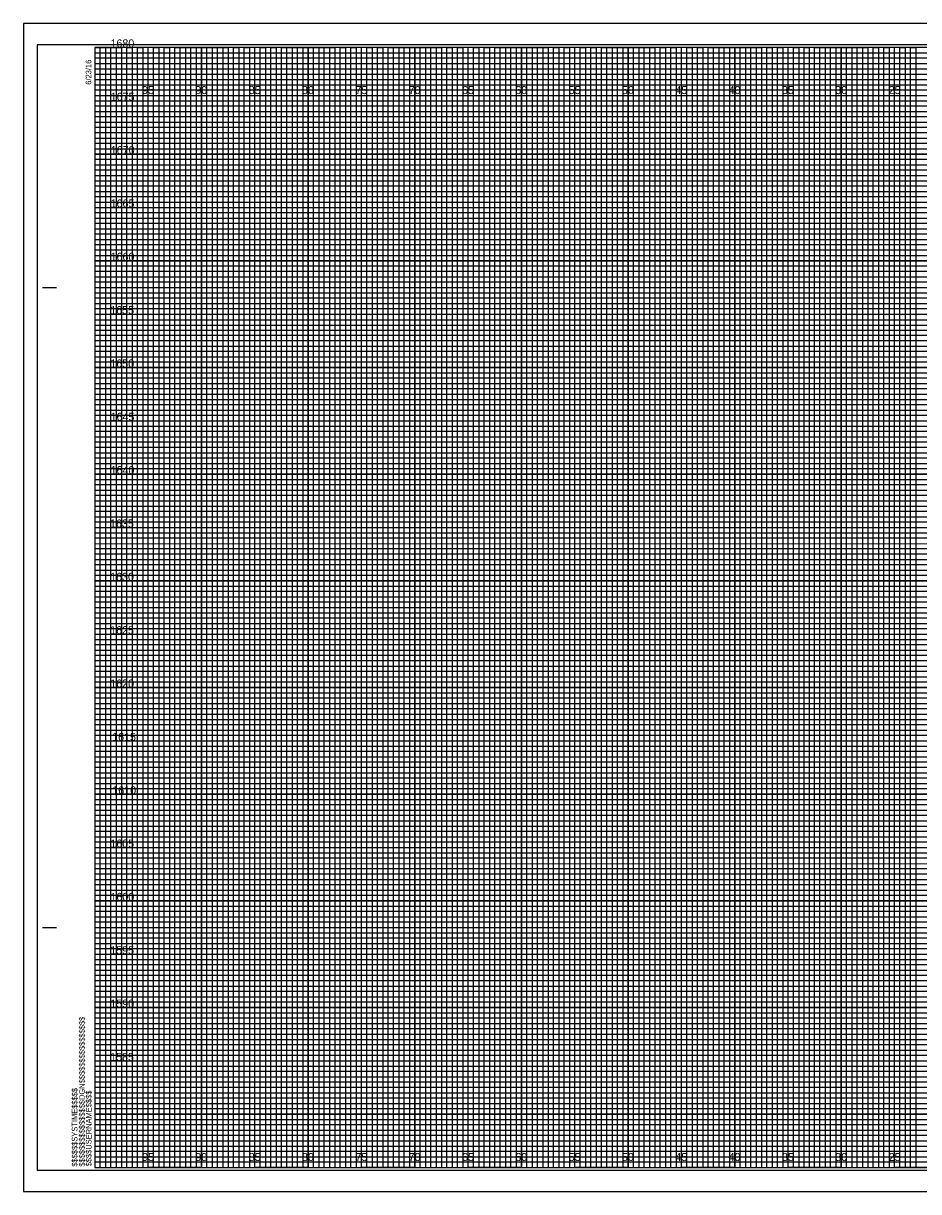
# Model space of a CAD drawing. Extents: x -8289 to 162, y -2 to 23207.
# Drawn here: x -6.7 to 77.2, y 547.8 to 657.2 of the extents above; entities that cross this region are included whole.
import ezdxf

# ---------------------------------------------------------------- set-up
doc = ezdxf.new("R2010")
doc.units = 0
for name, color, linetype in [('Prop XS Elevation Labels', 7, 'Continuous'), ('Prop XS Offset Labels', 7, 'Continuous'), ('Sheet Cross Section CELL', 7, 'Continuous'), ('Sheet Cross Section Grid Major CELL', 7, 'Continuous'), ('Sheet Cross Section Grid Middle CELL', 7, 'Continuous'), ('Sheet Cross Section Grid Minor 1 CELL', 7, 'Continuous'), ('Sheet Cross Section Grid Minor 2 CELL', 7, 'Continuous'), ('Sheet Cutting Line CELL', 7, 'Continuous'), ('Sheet DOT Grid CELL', 7, 'Continuous'), ('Sheet Plot Border Inside CELL', 7, 'Continuous'), ('Sheet Plot Border Outside CELL', 7, 'Continuous')]:
    doc.layers.add(name, color=color, linetype=linetype)

msp = doc.modelspace()

# ---------------------------------------------------------------- linework, layer by layer
at = {"layer": 'Sheet Cross Section CELL'}
for p, q in [((-4.9, 632.5), (-3.65, 632.5)), ((-4.85, 632.5), (-3.6, 632.5)), ((-4.9, 572.5), (-3.65, 572.5)), ((-4.85, 572.5), (-3.6, 572.5)), ((0, 550), (0, 550)), ((0, 550), (0, 550)), ((0, 550), (0, 550)), ((0, 550), (0, 550)), ((0, 550), (0, 550)), ((0, 550), (0, 550)), ((0, 550), (0, 550))]:
    msp.add_line(p, q, dxfattribs=at)
msp.add_lwpolyline([(160, 655), (0, 655), (0, 550), (160, 550)], close=True, dxfattribs=at)
at = {"layer": 'Sheet Cross Section Grid Major CELL'}
for p, q in [((5, 655), (0, 655)), ((5, 550), (5, 655)), ((15, 655), (10, 655)), ((10, 655), (10, 550)), ((15, 550), (15, 655)), ((25, 655), (20, 655)), ((20, 655), (20, 550)), ((25, 550), (25, 655)), ((35, 655), (30, 655)), ((30, 655), (30, 550)), ((35, 550), (35, 655)), ((45, 655), (40, 655)), ((40, 655), (40, 550)), ((45, 550), (45, 655)), ((55, 655), (50, 655)), ((50, 655), (50, 550)), ((55, 550), (55, 655)), ((65, 655), (60, 655)), ((60, 655), (60, 550)), ((65, 550), (65, 655)), ((75, 655), (70, 655)), ((70, 655), (70, 550)), ((75, 550), (75, 655)), ((10, 550), (5, 550)), ((20, 550), (15, 550)), ((30, 550), (25, 550)), ((40, 550), (35, 550)), ((50, 550), (45, 550)), ((60, 550), (55, 550)), ((70, 550), (65, 550)), ((80, 550), (75, 550))]:
    msp.add_line(p, q, dxfattribs=at)
for points in [[(0, 650), (160, 650), (160, 645), (0, 645)], [(0, 640), (160, 640), (160, 635), (0, 635)], [(0, 630), (160, 630), (160, 625), (0, 625)], [(0, 620), (160, 620), (160, 615), (0, 615)], [(0, 610), (160, 610), (160, 605), (0, 605)], [(0, 600), (160, 600), (160, 595), (0, 595)], [(0, 590), (160, 590), (160, 585), (0, 585)], [(0, 580), (160, 580), (160, 575), (0, 575)], [(0, 570), (160, 570), (160, 565), (0, 565)], [(0, 560), (160, 560), (160, 555), (0, 555)]]:
    msp.add_lwpolyline(points, dxfattribs=at)
at = {"layer": 'Sheet Cross Section Grid Middle CELL'}
for points in [[(0, 655), (2.5, 655), (2.5, 550), (7.5, 550), (7.5, 655), (12.5, 655), (12.5, 550), (17.5, 550), (17.5, 655), (22.5, 655), (22.5, 550), (27.5, 550), (27.5, 655), (32.5, 655), (32.5, 550), (37.5, 550), (37.5, 655), (42.5, 655), (42.5, 550), (47.5, 550), (47.5, 655), (52.5, 655), (52.5, 550), (57.5, 550), (57.5, 655), (62.5, 655), (62.5, 550), (67.5, 550), (67.5, 655), (72.5, 655), (72.5, 550), (77.5, 550)], [(0, 652.5), (137.5, 652.5)], [(0, 642.5), (160, 642.5), (160, 647.5), (0, 647.5)], [(0, 632.5), (160, 632.5), (160, 637.5), (0, 637.5)], [(0, 622.5), (160, 622.5), (160, 627.5), (0, 627.5)], [(0, 612.5), (160, 612.5), (160, 617.5), (0, 617.5)], [(0, 602.5), (160, 602.5), (160, 607.5), (0, 607.5)], [(0, 592.5), (160, 592.5), (160, 597.5), (0, 597.5)], [(0, 582.5), (160, 582.5), (160, 587.5), (0, 587.5)], [(0, 572.5), (160, 572.5), (160, 577.5), (0, 577.5)], [(0, 562.5), (160, 562.5), (160, 567.5), (0, 567.5)], [(0, 552.5), (160, 552.5), (160, 557.5), (0, 557.5)]]:
    msp.add_lwpolyline(points, dxfattribs=at)
at = {"layer": 'Sheet Cross Section Grid Minor 1 CELL'}
for p, q in [((0, 654.5), (130, 654.5)), ((130, 653.99), (0, 653.99)), ((0, 653.99), (0, 653.5)), ((0, 653.5), (130, 653.5)), ((130, 652.95), (0, 652.95)), ((0, 652.95), (0, 652)), ((0, 652), (160, 652))]:
    msp.add_line(p, q, dxfattribs=at)
for points in [[(0, 651.5), (135, 651.5), (160, 651.5), (160, 651), (0, 651)], [(0, 650.5), (160, 650.5), (160, 649.5), (0, 649.5)], [(0, 649), (160, 649), (160, 648.5), (0, 648.49)], [(0, 648), (160, 648), (160, 647), (0, 647)], [(0, 646.5), (160, 646.5), (160, 646), (0, 646)], [(0, 645.5), (160, 645.5), (160, 644.5), (0, 644.5)], [(0, 644), (160, 644), (160, 643.5), (0, 643.5)], [(0, 643), (160, 643), (160, 642), (0, 642)], [(0, 641.5), (160, 641.5), (160, 641), (0, 641)], [(0, 640.5), (160, 640.5), (160, 639.5), (0, 639.5)], [(0, 639), (160, 639), (160, 638.5), (0, 638.5)], [(0, 638), (160, 638), (160, 636.98), (160, 636.5), (160, 636), (0, 636)], [(0, 637), (160, 637), (160, 636.5), (0, 636.5)], [(0, 635.5), (160, 635.5), (160, 634.5), (0, 634.51)], [(0, 634.51), (160, 634.5), (160, 634), (0, 634)], [(0, 633.5), (160, 633.5), (160, 633), (0, 633)], [(0, 632), (160, 632), (160, 631.5), (0, 631.5)], [(0, 631), (160, 631), (160, 630.5), (0, 630.5)], [(-0.04, 629.45), (160, 629.45), (160, 628.94), (-0.04, 628.94)], [(0, 628.5), (160, 628.5), (160, 628), (0, 628)], [(0, 627), (160, 627), (160, 626.5), (0, 626.5)], [(0, 626), (160, 626), (160, 625.5), (0, 625.5)], [(0, 624.5), (160, 624.5), (160, 624), (0, 624)], [(0, 623.5), (160, 623.5), (160, 623), (0, 623)], [(0, 622), (160, 622), (160, 621.5), (0, 621.5)], [(0, 621), (160, 621), (160, 620.5), (0, 620.5)], [(0, 619.5), (160, 619.5), (160, 618.99), (0, 619)], [(0, 618.5), (160, 618.5), (160, 618), (0, 618)], [(0, 617), (160, 617), (160, 616.5), (0, 616.5)], [(0, 616), (160, 616), (160, 615.5), (0, 615.5)], [(0, 614.5), (160, 614.5), (160, 614), (0, 614)], [(0, 613.5), (160, 613.5), (160, 613), (0, 613)], [(0, 612), (160, 612), (160, 611.5), (0, 611.5)], [(0, 611), (160, 611), (160, 610.5), (0, 610.5)], [(0, 609.5), (160, 609.5), (160, 609), (0, 609)], [(0, 608.5), (160.03, 608.46), (160, 608), (0, 608)], [(0, 607), (160, 607), (160, 606.5), (0, 606.5)], [(0, 606), (160, 606), (160, 605.5), (0, 605.5)], [(0, 604.5), (160, 604.5), (160, 604), (0, 604)], [(0, 603.5), (160, 603.5), (160, 603), (0, 603)], [(0, 602), (160, 602), (160, 601.5), (0, 601.5)], [(0, 601), (160, 601), (160, 600.5), (0, 600.5)], [(0, 599.5), (160, 599.5), (160, 599), (0, 599)], [(0, 598.5), (160, 598.5), (160, 598), (0, 598)], [(0, 597), (160, 597), (160, 596.5), (0, 596.5)], [(0, 596), (160, 596), (160, 595.5), (0, 595.5)], [(0, 594.5), (160, 594.5), (160, 594), (0, 594)], [(0, 593.5), (160, 593.5), (160, 593), (0, 593)], [(0, 592), (160, 592), (160, 591.5), (0, 591.5)], [(0, 591), (160, 591), (160, 590.5), (0, 590.5)], [(0, 589.5), (160, 589.5), (160, 588.99), (0, 589)], [(0, 588.5), (160, 588.5), (160, 588), (0, 588)], [(0, 587), (160, 587), (160, 586.5), (0, 586.5)], [(0, 586), (160, 586), (160, 585.5), (0, 585.5)], [(0, 584.5), (160, 584.5), (160, 584), (0, 584)], [(0, 583.5), (160, 583.5), (160, 583), (0, 583)], [(0, 582), (160, 582), (160, 581.5), (0, 581.5)], [(0, 581), (160, 581), (160, 580.5), (0, 580.5)], [(0, 579.5), (160, 579.5), (160, 579), (0, 579)], [(0, 578.5), (160.03, 578.46), (160, 578), (0, 578)], [(0, 577), (160, 577), (160, 576.5), (0, 576.5)], [(0, 576), (160, 576), (160, 575.5), (0, 575.5)], [(0, 574.5), (160, 574.5), (160, 574), (0, 574)], [(0, 573.5), (160, 573.5), (160, 573), (0, 573)], [(0, 572), (160, 572), (160, 571.5), (0, 571.5)], [(0, 571), (160, 571), (160, 570.5), (0, 570.5)], [(0, 569.5), (160, 569.5), (160, 569), (0, 569)], [(0, 568.5), (160, 568.5), (160, 568), (0, 568)], [(0, 567), (160, 567), (160, 566.5), (0, 566.5)], [(0, 566), (160, 566), (160, 565.5), (0, 565.5)], [(0, 564.5), (160, 564.5), (160, 564), (0, 564)], [(0, 563.5), (160, 563.5), (160, 563), (0, 563)], [(0, 562), (160, 562), (160, 561.5), (0, 561.5)], [(0, 561), (160, 561), (160, 560.5), (0, 560.5)], [(0, 559.5), (160, 559.5), (160, 559), (0, 559)], [(0, 558.5), (160, 558.5), (160, 558), (0, 558)], [(0, 557), (160, 557), (160, 556.5), (0, 556.5)], [(0, 556), (160, 556), (160, 555.5), (0, 555.5)], [(0, 554.5), (160, 554.5), (160, 554), (0, 554)], [(0, 553.5), (160, 553.5), (160, 553), (0, 553)], [(0, 552), (160, 552), (160, 551.5), (0, 551.5)], [(0, 551), (160, 551), (160, 550.5), (0, 550.5)]]:
    msp.add_lwpolyline(points, dxfattribs=at)
at = {"layer": 'Sheet Cross Section Grid Minor 2 CELL'}
for points in [[(0, 550), (0.5, 550), (0.5, 655), (1, 655), (1, 550)], [(1, 550), (1.5, 550), (1.5, 655), (2, 655), (2, 550)], [(2.5, 550), (3, 550), (3, 655), (3.5, 655), (3.5, 550)], [(3.5, 550), (4, 550), (4, 655), (4.5, 655), (4.5, 550)], [(5, 550), (5.5, 550), (5.5, 655), (6, 655), (6, 550)], [(6, 550), (6.5, 550), (6.5, 655), (7, 655), (7, 550)], [(7.5, 550), (8, 550), (8, 655), (8.5, 655), (8.5, 550)], [(8.5, 550), (9, 550), (9, 655), (9.5, 655), (9.5, 550)], [(10, 550), (10.5, 550), (10.5, 655), (11, 655), (11, 550)], [(11, 550), (11.5, 550), (11.5, 655), (12, 655), (12, 550)], [(12.5, 550), (13, 550), (13, 655), (13.5, 655), (13.5, 550)], [(13.5, 550), (14, 550), (14, 655), (14.5, 655), (14.5, 550)], [(15, 550), (15.5, 550), (15.5, 655), (16, 655), (16, 550)], [(16, 550), (16.5, 550), (16.5, 655), (17, 655), (17, 550)], [(17.5, 550), (18, 550), (18, 655), (18.5, 655), (18.5, 550)], [(18.5, 550), (19, 550), (19, 655), (19.5, 655), (19.5, 550)], [(20, 550), (20.5, 550), (20.5, 655), (21, 655), (21, 550)], [(21, 550), (21.5, 550), (21.5, 655), (22, 655), (22, 550)], [(22.5, 550), (23, 550), (23, 655), (23.5, 655), (23.5, 550)], [(23.5, 550), (24, 550), (24, 655), (24.5, 655), (24.5, 550)], [(25, 550), (25.5, 550), (25.5, 655), (26, 655), (26, 550)], [(26, 550), (26.5, 550), (26.5, 655), (27, 655), (27, 550)], [(27.5, 550), (28, 550), (28, 655), (28.5, 655), (28.5, 550)], [(28.5, 550), (29, 550), (29, 655), (29.5, 655), (29.5, 550)], [(30, 550), (30.5, 550), (30.5, 655), (31, 655), (31, 550)], [(31, 550), (31.5, 550), (31.5, 655), (32, 655), (32, 550)], [(32.5, 550), (33, 550), (33, 655), (33.5, 655), (33.5, 550)], [(33.5, 550), (34, 550), (34, 655), (34.5, 655), (34.5, 550)], [(35, 550), (35.5, 550), (35.5, 655), (36, 655), (36, 550)], [(36, 550), (36.5, 550), (36.5, 655), (37, 655), (37, 550)], [(37.5, 550), (38, 550), (38, 655), (38.5, 655), (38.5, 550)], [(38.5, 550), (39, 550), (39, 655), (39.5, 655), (39.5, 550)], [(40, 550), (40.5, 550), (40.5, 655), (41, 655), (41, 550)], [(41, 550), (41.5, 550), (41.5, 655), (42, 655), (42, 550)], [(42.5, 550), (43, 550), (43, 655), (43.5, 655), (43.5, 550)], [(43.5, 550), (44, 550), (44, 655), (44.5, 655), (44.5, 550)], [(45, 550), (45.5, 550), (45.5, 655), (46, 655), (46, 550)], [(46, 550), (46.5, 550), (46.5, 655), (47, 655), (47, 550)], [(47.5, 550), (48, 550), (48, 655), (48.5, 655), (48.5, 550)], [(48.5, 550), (49, 550), (49, 655), (49.5, 655), (49.5, 550)], [(50, 550), (50.5, 550), (50.5, 655), (51, 655), (51, 550)], [(51, 550), (51.5, 550), (51.5, 655), (52, 655), (52, 550)], [(52.5, 550), (53, 550), (53, 655), (53.5, 655), (53.5, 550)], [(53.5, 550), (54, 550), (54, 655), (54.5, 655), (54.5, 550)], [(55, 550), (55.5, 550), (55.5, 655), (56, 655), (56, 550)], [(56, 550), (56.5, 550), (56.5, 655), (57, 655), (57, 550)], [(57.5, 550), (58, 550), (58, 655), (58.5, 655), (58.5, 550)], [(58.5, 550), (59, 550), (59, 655), (59.5, 655), (59.5, 550)], [(60, 550), (60.5, 550), (60.5, 655), (61, 655), (61, 550)], [(61, 550), (61.5, 550), (61.5, 655), (62, 655), (62, 550)], [(62.5, 550), (63, 550), (63, 655), (63.5, 655), (63.5, 550)], [(63.5, 550), (64, 550), (64, 655), (64.5, 655), (64.5, 550)], [(65, 550), (65.5, 550), (65.5, 655), (66, 655), (66, 550)], [(66, 550), (66.5, 550), (66.5, 655), (67, 655), (67, 550)], [(67.5, 550), (68, 550), (68, 655), (68.5, 655), (68.5, 550)], [(68.5, 550), (69, 550), (69, 655), (69.5, 655), (69.5, 550)], [(70, 550), (70.5, 550), (70.5, 655), (71, 655), (71, 550)], [(71, 550), (71.5, 550), (71.5, 655), (72, 655), (72, 550)], [(72.5, 550), (73, 550), (73, 655), (73.5, 655), (73.5, 550)], [(73.5, 550), (74, 550), (74, 655), (74.5, 655), (74.5, 550)], [(75, 550), (75.5, 550), (75.5, 655), (76, 655), (76, 550)], [(76, 550), (76.5, 550), (76.5, 655), (77, 655), (77, 550)]]:
    msp.add_lwpolyline(points, dxfattribs=at)
at = {"layer": 'Sheet Cutting Line CELL'}
for p, q in [((161.65, 657.25), (-6.7, 657.25)), ((-6.7, 657.25), (-6.7, 547.75)), ((-6.7, 547.75), (161.65, 547.75))]:
    msp.add_line(p, q, dxfattribs=at)
at = {"layer": 'Sheet DOT Grid CELL'}
for p, q in [((5, 550), (5, 655)), ((10, 550), (10, 655)), ((15, 550), (15, 655)), ((20, 550), (20, 655)), ((25, 550), (25, 655)), ((30, 550), (30, 655)), ((35, 550), (35, 655)), ((40, 550), (40, 655)), ((45, 550), (45, 655)), ((50, 550), (50, 655)), ((55, 550), (55, 655)), ((60, 550), (60, 655)), ((65, 550), (65, 655)), ((70, 550), (70, 655)), ((75, 550), (75, 655)), ((0, 650), (160, 650)), ((0, 645), (160, 645)), ((0, 640), (160, 640)), ((0, 635), (160, 635)), ((0, 630), (160, 630)), ((0, 625), (160, 625)), ((0, 620), (160, 620)), ((0, 615), (160, 615)), ((0, 610), (160, 610)), ((0, 605), (160, 605)), ((0, 600), (160, 600)), ((0, 595), (160, 595)), ((0, 590), (160, 590)), ((0, 585), (160, 585)), ((0, 580), (160, 580)), ((0, 575), (160, 575)), ((0, 570), (160, 570)), ((0, 565), (160, 565)), ((0, 560), (160, 560)), ((0, 555), (160, 555))]:
    msp.add_line(p, q, dxfattribs=at)
at = {"layer": 'Sheet Plot Border Inside CELL'}
msp.add_lwpolyline([(-5.4, 549.75), (161.2, 549.75), (161.2, 655.25), (-5.4, 655.25)], close=True, dxfattribs=at)
at = {"layer": 'Sheet Plot Border Outside CELL'}
msp.add_lwpolyline([(-6.7, 547.75), (161.65, 547.75), (161.65, 657.25), (-6.7, 657.25)], close=True, dxfattribs=at)

# ---------------------------------------------------------------- texts
at = {"layer": 'Prop XS Elevation Labels'}
for s, p in [('1680', (1.47, 655)), ('1675', (1.49, 650)), ('1670', (1.5, 645)), ('1665', (1.48, 640)), ('1660', (1.48, 635)), ('1655', (1.45, 630)), ('1650', (1.46, 625)), ('1645', (1.48, 620)), ('1640', (1.48, 615)), ('1635', (1.43, 610)), ('1630', (1.44, 605)), ('1625', (1.44, 600)), ('1620', (1.45, 595)), ('1615', (1.63, 590)), ('1610', (1.64, 585)), ('1605', (1.46, 580)), ('1600', (1.47, 575)), ('1595', (1.45, 570)), ('1590', (1.46, 565)), ('1585', (1.44, 560))]:
    msp.add_text(s, height=0.75, dxfattribs=at).set_placement(p)
at = {"layer": 'Prop XS Offset Labels'}
for s, p in [('95', (4.44, 650.62)), ('90', (9.43, 650.62)), ('85', (14.44, 650.62)), ('80', (19.43, 650.62)), ('75', (24.44, 650.62)), ('70', (29.43, 650.62)), ('65', (34.44, 650.62)), ('60', (39.43, 650.62)), ('55', (44.44, 650.62)), ('50', (49.43, 650.62)), ('45', (54.44, 650.62)), ('40', (59.43, 650.62)), ('35', (64.44, 650.62)), ('30', (69.43, 650.62)), ('25', (74.44, 650.62)), ('95', (4.44, 550.62)), ('90', (9.43, 550.62)), ('85', (14.44, 550.62)), ('80', (19.43, 550.62)), ('75', (24.44, 550.62)), ('70', (29.43, 550.62)), ('65', (34.44, 550.62)), ('60', (39.43, 550.62)), ('55', (44.44, 550.62)), ('50', (49.43, 550.62)), ('45', (54.44, 550.62)), ('40', (59.43, 550.62)), ('35', (64.44, 550.62)), ('30', (69.43, 550.62)), ('25', (74.44, 550.62))]:
    msp.add_text(s, height=0.75, dxfattribs=at).set_placement(p)
at = {"layer": 'Sheet Cross Section CELL'}
for s, p in [('6/23/16', (-0.33, 651.5)), ('$$$$$$$$$$$$$$$$DGN$$$$$$$$$$$$$$$$', (-0.94, 550.09)), ('$$$$$$SYSTIME$$$$$', (-1.63, 550.09)), ('$$$$USERNAME$$$$', (-0.31, 550.12))]:
    msp.add_text(s, height=0.525, rotation=90, dxfattribs=at).set_placement(p)

doc.saveas('drawing.dxf')
